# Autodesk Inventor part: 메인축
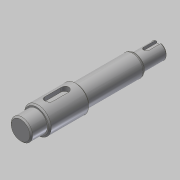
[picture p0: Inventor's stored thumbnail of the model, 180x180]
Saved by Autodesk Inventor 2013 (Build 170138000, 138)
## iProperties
Created: 2019-03
Part Number: 메인축
Material: 강철, 연강
Document SubType Name: Modeling
Designer: mduedu
Density: 1 g/cm^3
Author: mduedu
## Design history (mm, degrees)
sketch "스케치1"
  geometry: L1 (0, 0)-(12, 0); L2 (12, 0)-(12, 8); L3 (12, 8)-(0, 8); L4 (0, 8)-(0, 0); L5 (12, 0)-(42, 0); L6 (42, 0)-(42, 10); L7 (42, 10)-(12, 10); L8 (12, 10)-(12, 0); L9 (42, 0)-(86, 0); L10 (86, 0)-(86, 8); L11 (86, 8)-(42, 8); L12 (42, 8)-(42, 0); L13 (86, 0)-(104, 0); L14 (104, 0)-(104, 6); L15 (104, 6)-(86, 6); L16 (86, 6)-(86, 0)
  constraints: 32 end point, 8 parallel, 4 horizontal, 4 perpendicular
  dimensions: "d0" = 16 diameter of L3 L1; "d2" = 20 diameter of L7 L5; "d3" = 16 diameter of L11 L9; "d4" = 12 diameter of L15 L13; "d5" = 12 distance of L2.end L3.end; "d6" = 30 distance of L6.end L7.end; "d7" = 86 distance between parallel lines of L10 L4; "d8" = 104 distance between parallel lines of L14 L4
revolve "회전1" sketch "스케치1" stored, may be unused: angle "d9" = 90 deg
node "작업 평면1"
sketch "스케치2" dims "d10" = 18
  geometry: L1 (6, -3)-(-6, -3); L2 (-6, -3)-(-6, 3); L3 (-6, 3)-(6, 3); L4 (6, 3)-(6, -3); L5 (15, 10)-(15, -10) reference; 3 further points
  constraints: 8 end point, 2 midpoint, 2 parallel, 2 vertical alignment, 1 horizontal, 1 horizontal alignment, 1 perpendicular, 4 other
  dimensions: "d12" = 6 distance between parallel lines of L3 L1; "d13" = 6 dimension on L5
extrude "돌출1" cut sketch "스케치2" distance "d14" = 3.5; taper "d15" = 0 deg
node "작업 평면2"
sketch "스케치3"
  geometry: L1 (-9, 6)-(-9, -6) reference; L2 (1, -2)-(-9, -2); L3 (1, 2)-(-9, 2); A1 r 2 centre (1, 0) between (1, -2) and (1, 2); 2 further points
  constraints: 4 end point, 2 point on circle, 2 point on line, 2 tangent, 1 centre point, 1 horizontal alignment, 1 midpoint, 1 parallel, 1 perpendicular
  dimensions: "d16" = 12 dimension on A1 L1; "d17" = 4 distance between parallel lines of L3 L2
extrude "돌출2" cut sketch "스케치3" distance "d18" = 2.5; taper "d19" = 0 deg
chamfer "모따기1" distance "d20" = 1; stored, may be unused: second distance "d21" = 2, angle "d22" = 45 deg
chamfer "모따기2" distance "d23" = 1; stored, may be unused: second distance "d24" = 2, angle "d25" = 45 deg
chamfer "모따기3" distance "d26" = 1.73; stored, may be unused: second distance "d27" = 2, angle "d28" = 30 deg
fillet "모깎기2" dims "d31" = 1, "d32" = 2
node "솔리드1"
